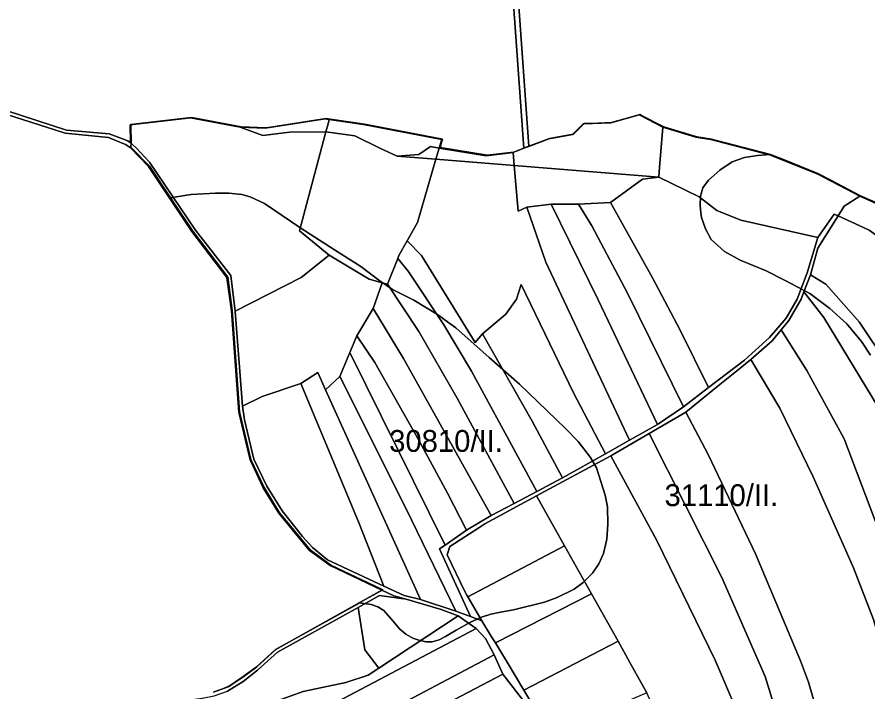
# Model space of a CAD drawing. Extents: x -535894 to -532827, y -1165802 to -1163635.
# Drawn here: x -535071 to -534487, y -1164561 to -1164098 of the extents above; entities that cross this region are included whole.
import ezdxf

# ---------------------------------------------------------------- set-up
doc = ezdxf.new("R2010")
doc.units = 0
for name, color, linetype in [('BPEJ_s', 7, 'Continuous'), ('orna_s', 7, 'Continuous'), ('ostatni_s', 7, 'Continuous'), ('PUPFL_s', 7, 'Continuous'), ('trav_porost_s', 7, 'Continuous')]:
    doc.layers.add(name, color=color, linetype=linetype)

msp = doc.modelspace()

# ---------------------------------------------------------------- linework, layer by layer
at = {"layer": 'BPEJ_s'}
for points in [[(-534935.616, -1164561.701), (-534930.369, -1164559.695), (-534925.946, -1164558.004), (-534925.446, -1164557.813), (-534915.983, -1164551.622), (-534906.33, -1164544.336), (-534893.16, -1164532.39), (-534837.757, -1164501.484), (-534836.099, -1164500.559), (-534827.97, -1164501.66), (-534823.27, -1164503.17), (-534819.077, -1164505.775), (-534813, -1164512.81), (-534808.069, -1164518.519), (-534803.96, -1164521.97), (-534799.317, -1164524.66), (-534795.2, -1164526.19), (-534790.38, -1164527.18), (-534786.08, -1164527.14), (-534781.1, -1164525.95), (-534776.72, -1164523.6), (-534769.44, -1164519.18), (-534759.64, -1164513.8), (-534752.19, -1164510.38), (-534745.78, -1164508.19), (-534739.126, -1164506.93), (-534730.05, -1164505.211), (-534708.87, -1164499.991), (-534700.23, -1164496.84), (-534688.52, -1164491.03), (-534682.31, -1164486.49), (-534675.94, -1164480.12), (-534671.48, -1164473.67), (-534668.28, -1164466.511), (-534665.98, -1164456.62), (-534665.338, -1164446.485), (-534665.67, -1164434.48), (-534667.181, -1164426.52), (-534673.149, -1164407.64), (-534677.21, -1164400.48), (-534685.81, -1164389.49), (-534694.34, -1164380.73), (-534725.95, -1164350.22), (-534746.741, -1164331.83), (-534769.679, -1164311.539), (-534774.451, -1164308.019), (-534782.34, -1164302.2), (-534798.58, -1164292.49), (-534813.16, -1164284.999), (-534822.64, -1164278.71), (-534834.98, -1164269.391), (-534853.14, -1164257.76), (-534876.848, -1164242.577), (-534901, -1164225.91), (-534910.96, -1164221.29), (-534916.61, -1164219.85), (-534925.61, -1164218.82), (-534934.669, -1164218.82), (-534951.41, -1164219.69), (-534961.495, -1164221.347), (-534965.667, -1164222.032), (-534980.193, -1164200.238), (-534992.796, -1164187.266), (-534992.657, -1164184.123), (-534992.864, -1164172.606), (-534992.881, -1164171.663), (-534951.283, -1164166.804), (-534917.176, -1164173.315), (-534900.166, -1164173.97), (-534899.694, -1164173.897), (-534858.802, -1164167.607), (-534856.129, -1164167.995), (-534832.542, -1164171.394), (-534778.846, -1164181.704), (-534779.48, -1164183.877), (-534780.07, -1164185.879), (-534780.579, -1164187.608), (-534748.266, -1164192.874), (-534729.874, -1164190.604), (-534722.509, -1164187.801), (-534705.313, -1164181.264), (-534689.018, -1164178.399), (-534684.237, -1164173.666), (-534681.635, -1164171.091), (-534672.23, -1164170.724), (-534662.759, -1164170.354), (-534644.816, -1164165.28), (-534643.356, -1164164.867)], [(-534626.941, -1164173.233), (-534642.191, -1164165.461), (-534643.356, -1164164.867), (-534644.816, -1164165.28), (-534662.759, -1164170.354), (-534672.23, -1164170.724), (-534681.635, -1164171.091), (-534684.237, -1164173.666), (-534689.018, -1164178.399), (-534705.313, -1164181.264), (-534722.509, -1164187.801), (-534729.874, -1164190.604), (-534748.266, -1164192.874), (-534780.579, -1164187.608), (-534780.07, -1164185.879), (-534779.48, -1164183.877), (-534778.846, -1164181.704), (-534832.542, -1164171.394), (-534856.129, -1164167.995), (-534858.802, -1164167.607), (-534899.694, -1164173.897), (-534900.166, -1164173.97), (-534917.176, -1164173.315), (-534951.283, -1164166.804), (-534992.881, -1164171.663), (-534992.864, -1164172.606), (-534992.657, -1164184.123), (-534992.796, -1164187.266), (-534980.193, -1164200.238), (-534965.667, -1164222.032), (-534964.702, -1164223.481), (-534950.412, -1164244.92), (-534926.32, -1164276.615), (-534923.23, -1164299.595), (-534918.262, -1164369.183), (-534910.455, -1164401.933), (-534901.354, -1164421.155), (-534890.744, -1164438.654), (-534869.801, -1164464.022), (-534855.445, -1164474.524), (-534825.523, -1164488.851), (-534819.921, -1164491.534), (-534836.099, -1164500.559), (-534837.757, -1164501.484), (-534893.16, -1164532.39), (-534906.33, -1164544.336), (-534915.983, -1164551.622), (-534925.446, -1164557.813), (-534925.946, -1164558.004), (-534930.369, -1164559.695), (-534935.616, -1164561.701)], [(-534643.356, -1164164.867), (-534642.191, -1164165.461), (-534626.941, -1164173.233), (-534604.257, -1164180.053), (-534594.057, -1164181.691), (-534590.665, -1164182.581), (-534553.695, -1164192.208)], [(-534478.19, -1164226.769), (-534491.819, -1164220.783), (-534511.744, -1164210.267), (-534521.117, -1164205.32), (-534544.673, -1164195.839), (-534553.695, -1164192.208), (-534590.665, -1164182.581), (-534594.057, -1164181.691), (-534604.257, -1164180.053), (-534626.941, -1164173.233)], [(-534484.96, -1164330.27), (-534491.235, -1164320.721), (-534501.29, -1164308.689), (-534512.831, -1164298.076), (-534526.7, -1164287.75), (-534543.58, -1164278.99), (-534556.669, -1164272.198), (-534574.4, -1164264.97), (-534585.15, -1164258.92), (-534594.3, -1164250.647), (-534598.37, -1164243.47), (-534600.979, -1164235.643), (-534601.393, -1164232.323), (-534602.001, -1164227.456), (-534601.72, -1164220.85), (-534600.201, -1164215.27), (-534596.14, -1164209.86), (-534588.42, -1164203.01), (-534579.867, -1164197.234), (-534571.45, -1164194.33), (-534562.65, -1164192.974), (-534553.695, -1164192.208), (-534544.673, -1164195.839), (-534521.117, -1164205.32), (-534511.744, -1164210.267), (-534491.819, -1164220.783), (-534478.19, -1164226.769)], [(-534553.695, -1164192.208), (-534562.65, -1164192.974), (-534571.45, -1164194.33), (-534579.867, -1164197.234), (-534588.42, -1164203.01), (-534596.14, -1164209.86), (-534600.201, -1164215.27), (-534601.72, -1164220.85), (-534602.001, -1164227.456), (-534601.393, -1164232.323), (-534600.979, -1164235.643), (-534598.37, -1164243.47), (-534594.3, -1164250.647), (-534585.15, -1164258.92), (-534574.4, -1164264.97), (-534556.669, -1164272.198), (-534543.58, -1164278.99), (-534526.7, -1164287.75), (-534512.831, -1164298.076), (-534501.29, -1164308.689), (-534491.235, -1164320.721), (-534484.96, -1164330.27)]]:
    msp.add_lwpolyline(points, dxfattribs=at)
msp.add_lwpolyline([(-534836.099, -1164500.559), (-534819.921, -1164491.534), (-534825.523, -1164488.851), (-534855.445, -1164474.524), (-534869.801, -1164464.022), (-534890.744, -1164438.654), (-534901.354, -1164421.155), (-534910.455, -1164401.933), (-534918.262, -1164369.183), (-534923.23, -1164299.595), (-534926.32, -1164276.615), (-534950.412, -1164244.92), (-534964.702, -1164223.481), (-534965.667, -1164222.032), (-534961.495, -1164221.347), (-534951.41, -1164219.69), (-534934.669, -1164218.82), (-534925.61, -1164218.82), (-534916.61, -1164219.85), (-534910.96, -1164221.29), (-534901, -1164225.91), (-534876.848, -1164242.577), (-534853.14, -1164257.76), (-534834.98, -1164269.391), (-534822.64, -1164278.71), (-534813.16, -1164284.999), (-534798.58, -1164292.49), (-534782.34, -1164302.2), (-534774.451, -1164308.019), (-534769.679, -1164311.539), (-534746.741, -1164331.83), (-534725.95, -1164350.22), (-534694.34, -1164380.73), (-534685.81, -1164389.49), (-534677.21, -1164400.48), (-534673.149, -1164407.64), (-534667.181, -1164426.52), (-534665.67, -1164434.48), (-534665.338, -1164446.485), (-534665.98, -1164456.62), (-534668.28, -1164466.511), (-534671.48, -1164473.67), (-534675.94, -1164480.12), (-534682.31, -1164486.49), (-534688.52, -1164491.03), (-534700.23, -1164496.84), (-534708.87, -1164499.991), (-534730.05, -1164505.211), (-534739.126, -1164506.93), (-534745.78, -1164508.19), (-534752.19, -1164510.38), (-534759.64, -1164513.8), (-534769.44, -1164519.18), (-534776.72, -1164523.6), (-534781.1, -1164525.95), (-534786.08, -1164527.14), (-534790.38, -1164527.18), (-534795.2, -1164526.19), (-534799.317, -1164524.66), (-534803.96, -1164521.97), (-534808.069, -1164518.519), (-534813, -1164512.81), (-534819.077, -1164505.775), (-534823.27, -1164503.17), (-534827.97, -1164501.66)], close=True, dxfattribs=at)
at = {"layer": 'orna_s'}
for points in [[(-534951.85, -1164167.07), (-534917.74, -1164173.57), (-534902.24, -1164179.24), (-534883.98, -1164176.96), (-534858.94, -1164176.7), (-534877.07, -1164244.78), (-534856.73, -1164261.58), (-534875.86, -1164276.92), (-534921.15, -1164300.08), (-534924.21, -1164275.5), (-534948.43, -1164244.35), (-534980.14, -1164197.64), (-534989.29, -1164187.7), (-534993.22, -1164184.39), (-534993.44, -1164171.93)], [(-534858.94, -1164176.7), (-534839.04, -1164179.37), (-534822, -1164188.03), (-534810.06, -1164193.46), (-534783.41, -1164195.59), (-534796.15, -1164238.96), (-534803.19, -1164251.66), (-534808.78, -1164261.74), (-534809.59, -1164263.76), (-534816.62, -1164281.45), (-534820.28, -1164280.47), (-534829.26, -1164278.07), (-534856.73, -1164261.58), (-534877.07, -1164244.78)], [(-534783.41, -1164195.59), (-534729.66, -1164199.87), (-534726.97, -1164231.26), (-534720.99, -1164228.44), (-534707.84, -1164266.29), (-534650.37, -1164388.64), (-534666.96, -1164397.98), (-534688.94, -1164356.11), (-534724.82, -1164281.62), (-534728, -1164291.7), (-534735.4, -1164302.05), (-534751.45, -1164315.56), (-534756.49, -1164321.41), (-534793.3, -1164261.64), (-534803.19, -1164251.66), (-534796.15, -1164238.96)], [(-534729.66, -1164199.87), (-534630.4, -1164207.78), (-534641.63, -1164209.34), (-534663.54, -1164225.41), (-534685.41, -1164226.35), (-534704.16, -1164226.38), (-534720.99, -1164228.44), (-534726.97, -1164231.26)], [(-534630.4, -1164207.78), (-534602.67, -1164221.46), (-534590.55, -1164230.7), (-534573.95, -1164237.35), (-534521.14, -1164249.39), (-534528.41, -1164273.53), (-534535.31, -1164291.72), (-534542.92, -1164304.7), (-534554.35, -1164317.99), (-534571.47, -1164333.62), (-534596.12, -1164352.56), (-534615.63, -1164313.03), (-534634.67, -1164277.03), (-534663.54, -1164225.41), (-534641.63, -1164209.34)], [(-534704.16, -1164226.38), (-534672.04, -1164292.08), (-534631.34, -1164377.92), (-534650.37, -1164388.64), (-534707.84, -1164266.29), (-534720.99, -1164228.44)], [(-534685.41, -1164226.35), (-534676.36, -1164241.4), (-534651.82, -1164287.55), (-534613.33, -1164365.78), (-534631.34, -1164377.92), (-534672.04, -1164292.08), (-534704.16, -1164226.38)], [(-534663.54, -1164225.41), (-534634.67, -1164277.03), (-534615.63, -1164313.03), (-534596.12, -1164352.56), (-534613.33, -1164365.78), (-534651.82, -1164287.55), (-534676.36, -1164241.4), (-534685.41, -1164226.35)], [(-534507.27, -1164234.42), (-534521.16, -1164256.66), (-534526.13, -1164274.97), (-534530.72, -1164286.68), (-534532.67, -1164291.64), (-534540.94, -1164306.3), (-534546.29, -1164312.84), (-534552.41, -1164320.35), (-534567.13, -1164333.28), (-534578.03, -1164342.06), (-534589.62, -1164351.4), (-534611.82, -1164369.29), (-534636.96, -1164383.97), (-534663.27, -1164399.34), (-534714.26, -1164426.9), (-534749.86, -1164446.14), (-534753.21, -1164448.33), (-534773.86, -1164461.8), (-534775.57, -1164467.46), (-534763.52, -1164492.61), (-534762.09, -1164495.12), (-534761.39, -1164496.32), (-534751.97, -1164512.8), (-534759.6, -1164509.93), (-534780.87, -1164463.39), (-534777.12, -1164460.78), (-534762.46, -1164450.55), (-534745.42, -1164440.45), (-534729.71, -1164432.15), (-534714.14, -1164423.92), (-534696.51, -1164414.6), (-534666.96, -1164397.98), (-534650.37, -1164388.64), (-534631.34, -1164377.92), (-534613.33, -1164365.78), (-534596.12, -1164352.56), (-534571.47, -1164333.62), (-534554.35, -1164317.99), (-534542.92, -1164304.7), (-534535.31, -1164291.72), (-534528.41, -1164273.53), (-534521.14, -1164249.39), (-534509.85, -1164233.23)], [(-534485.85, -1164244.28), (-534469.68, -1164256.06), (-534441.39, -1164280.53), (-534439.7, -1164278.38), (-534420.68, -1164291.71), (-534381.33, -1164307.72), (-534380.51, -1164314.71), (-534392.48, -1164323.34), (-534409.97, -1164335.95), (-534429.42, -1164349.98), (-534454.21, -1164364.71), (-534492.77, -1164307.32), (-534515.72, -1164281.44), (-534526.13, -1164274.97), (-534521.16, -1164256.66), (-534507.27, -1164234.42)], [(-534793.3, -1164261.64), (-534756.49, -1164321.41), (-534751.45, -1164315.56), (-534717.41, -1164375.63), (-534696.51, -1164414.6), (-534714.14, -1164423.92), (-534758.85, -1164341.14), (-534778.05, -1164309.36), (-534802.47, -1164272.58), (-534809.59, -1164263.76), (-534808.78, -1164261.74), (-534803.19, -1164251.66)], [(-534875.86, -1164276.92), (-534856.73, -1164261.58), (-534829.26, -1164278.07), (-534820.28, -1164280.47), (-534826.58, -1164298.06), (-534837.63, -1164317), (-534842.42, -1164328.36), (-534849.36, -1164344.79), (-534859.13, -1164354.02), (-534864.46, -1164342.21), (-534876.21, -1164349.78), (-534902.82, -1164358.65), (-534916.14, -1164365.28), (-534921.15, -1164300.08)], [(-534809.59, -1164263.76), (-534802.47, -1164272.58), (-534778.05, -1164309.36), (-534758.85, -1164341.14), (-534714.14, -1164423.92), (-534729.71, -1164432.15), (-534768.7, -1164359.72), (-534795.14, -1164313.94), (-534816.62, -1164281.45)], [(-534526.13, -1164274.97), (-534515.72, -1164281.44), (-534492.77, -1164307.32), (-534454.21, -1164364.71), (-534429.42, -1164349.98), (-534416.02, -1164381.41), (-534395.29, -1164442.42), (-534374.06, -1164525.31), (-534335.46, -1164704.47), (-534321.03, -1164764.37), (-534369.38, -1164771.26), (-534395.1, -1164665.47), (-534403.85, -1164623.02), (-534425.95, -1164524.31), (-534441.36, -1164472.55), (-534468.86, -1164391.61), (-534480, -1164365.41), (-534516.93, -1164304.39), (-534530.72, -1164286.68)], [(-534816.62, -1164281.45), (-534795.14, -1164313.94), (-534768.7, -1164359.72), (-534729.71, -1164432.15), (-534745.42, -1164440.45), (-534805.69, -1164332.46), (-534826.58, -1164298.06), (-534820.28, -1164280.47)], [(-534728, -1164291.7), (-534724.82, -1164281.62), (-534688.94, -1164356.11), (-534666.96, -1164397.98), (-534696.51, -1164414.6), (-534717.41, -1164375.63), (-534751.45, -1164315.56), (-534735.4, -1164302.05)], [(-534532.67, -1164291.64), (-534530.72, -1164286.68), (-534516.93, -1164304.39), (-534480, -1164365.41), (-534468.86, -1164391.61), (-534441.36, -1164472.55), (-534425.95, -1164524.31), (-534403.85, -1164623.02), (-534395.1, -1164665.47), (-534369.38, -1164771.26), (-534394.4, -1164775.14), (-534435.14, -1164602.44), (-534447.18, -1164556.51), (-534458.51, -1164505.61), (-534503.01, -1164387.73), (-534528.59, -1164340.68), (-534546.29, -1164312.84), (-534540.94, -1164306.3)], [(-534826.58, -1164298.06), (-534805.69, -1164332.46), (-534745.42, -1164440.45), (-534762.46, -1164450.55), (-534775.49, -1164425.15), (-534794.91, -1164389.11), (-534825.45, -1164335.34), (-534837.63, -1164317)], [(-534552.41, -1164320.35), (-534546.29, -1164312.84), (-534528.59, -1164340.68), (-534503.01, -1164387.73), (-534458.51, -1164505.61), (-534447.18, -1164556.51), (-534435.14, -1164602.44), (-534394.4, -1164775.14), (-534417.97, -1164782.81), (-534422.37, -1164761.45), (-534445.23, -1164674.2), (-534452.73, -1164639.92), (-534475.43, -1164538.49), (-534482.99, -1164511.95), (-534496.61, -1164476.36), (-534524.39, -1164413.79), (-534547.27, -1164366.74), (-534567.13, -1164333.28)], [(-534837.63, -1164317), (-534825.45, -1164335.34), (-534794.91, -1164389.11), (-534775.49, -1164425.15), (-534762.46, -1164450.55), (-534777.12, -1164460.78), (-534842.42, -1164328.36)], [(-534842.42, -1164328.36), (-534777.12, -1164460.78), (-534780.87, -1164463.39), (-534759.6, -1164509.93), (-534769.82, -1164506.09), (-534803.97, -1164435.37), (-534849.36, -1164344.79)], [(-534578.03, -1164342.06), (-534567.13, -1164333.28), (-534547.27, -1164366.74), (-534524.39, -1164413.79), (-534496.61, -1164476.36), (-534482.99, -1164511.95), (-534475.43, -1164538.49), (-534452.73, -1164639.92), (-534445.23, -1164674.2), (-534422.37, -1164761.45), (-534417.97, -1164782.81), (-534464.01, -1164796.91), (-534483.14, -1164727.26), (-534507.98, -1164622.35), (-534527.6, -1164554.86), (-534532.98, -1164540.25), (-534563.85, -1164466.68), (-534596.51, -1164398.57), (-534611.82, -1164369.29), (-534589.62, -1164351.4)], [(-534864.46, -1164342.21), (-534859.13, -1164354.02), (-534793.9, -1164498.24), (-534805.09, -1164495.48), (-534819.12, -1164488.91), (-534836.46, -1164444.76), (-534876.21, -1164349.78)], [(-534849.36, -1164344.79), (-534803.97, -1164435.37), (-534769.82, -1164506.09), (-534770.38, -1164505.88), (-534793.9, -1164498.24), (-534859.13, -1164354.02)], [(-534876.21, -1164349.78), (-534836.46, -1164444.76), (-534819.12, -1164488.91), (-534857.75, -1164470.83), (-534868.09, -1164462.44), (-534875.04, -1164454.94), (-534889.06, -1164437.27), (-534899.57, -1164420.22), (-534908.44, -1164401.64), (-534914.8, -1164374.59), (-534916.14, -1164365.28), (-534902.82, -1164358.65)], [(-534636.96, -1164383.97), (-534611.82, -1164369.29), (-534596.51, -1164398.57), (-534563.85, -1164466.68), (-534532.98, -1164540.25), (-534527.6, -1164554.86), (-534507.98, -1164622.35), (-534483.14, -1164727.26), (-534464.01, -1164796.91), (-534487.57, -1164805.99), (-534533.79, -1164627.84), (-534557.27, -1164551.19), (-534587.12, -1164482.93)], [(-534663.27, -1164399.34), (-534636.96, -1164383.97), (-534587.12, -1164482.93), (-534557.27, -1164551.19), (-534533.79, -1164627.84), (-534487.57, -1164805.99), (-534495.37, -1164808.4), (-534503.46, -1164810.12), (-534512.61, -1164811.26), (-534519.96, -1164775.85), (-534529.51, -1164742.37), (-534548.57, -1164664.74), (-534575.39, -1164577.77), (-534591.62, -1164539.75), (-534631.7, -1164457.63)], [(-534714.26, -1164426.9), (-534663.27, -1164399.34), (-534631.7, -1164457.63), (-534591.62, -1164539.75), (-534575.39, -1164577.77), (-534548.57, -1164664.74), (-534529.51, -1164742.37), (-534519.96, -1164775.85), (-534512.61, -1164811.26), (-534562.14, -1164816.82), (-534585.02, -1164716.41), (-534592.87, -1164689.03), (-534598.52, -1164669.31), (-534600.76, -1164662.66), (-534607.61, -1164642.33), (-534611.82, -1164629.82), (-534620.54, -1164603.95), (-534622.31, -1164599.78), (-534633.48, -1164573.56), (-534638.57, -1164562.2), (-534650.14, -1164541.51), (-534658.33, -1164526.87), (-534676.64, -1164494.15), (-534695.08, -1164461.19)], [(-534749.86, -1164446.14), (-534714.26, -1164426.9), (-534695.08, -1164461.19), (-534761.39, -1164496.32), (-534762.09, -1164495.12), (-534763.52, -1164492.61), (-534775.57, -1164467.46), (-534773.86, -1164461.8), (-534753.21, -1164448.33)], [(-534695.08, -1164461.19), (-534676.64, -1164494.15), (-534742.58, -1164527.98), (-534745.16, -1164523.82), (-534751.97, -1164512.8), (-534761.39, -1164496.32)], [(-534803.86, -1164497.99), (-534779.71, -1164504.98), (-534768.01, -1164509.35), (-534822.67, -1164545.3), (-534832.14, -1164532.75), (-534836.85, -1164503.64), (-534822.13, -1164495.45)], [(-534658.33, -1164526.87), (-534723.13, -1164560.41), (-534734.51, -1164541.31), (-534738.99, -1164533.78), (-534742.58, -1164527.98), (-534676.64, -1164494.15)], [(-534836.85, -1164503.64), (-534832.14, -1164532.75), (-534822.67, -1164545.3), (-534830, -1164550.13), (-534845.17, -1164555.12), (-534874.58, -1164561.46), (-534901.23, -1164570.96), (-534933.74, -1164580.6), (-534950.39, -1164582.04), (-534954.11, -1164567.3), (-534943.8, -1164566.05), (-534935.73, -1164564.46), (-534926.58, -1164561.08), (-534915.74, -1164554.41), (-534905.82, -1164546.8), (-534892.07, -1164534.38)], [(-534768.01, -1164509.35), (-534755.68, -1164518.03), (-534901.21, -1164594.89), (-534994.2, -1164614.17), (-535000.27, -1164571.83), (-534999.95, -1164571.8), (-534954.11, -1164567.3), (-534950.39, -1164582.04), (-534933.74, -1164580.6), (-534901.23, -1164570.96), (-534874.58, -1164561.46), (-534845.17, -1164555.12), (-534830, -1164550.13), (-534822.67, -1164545.3)], [(-534755.68, -1164518.03), (-534749.42, -1164524.99), (-534743.38, -1164536.18), (-534894.51, -1164616.18), (-534991.15, -1164635.45), (-534994.2, -1164614.17), (-534901.21, -1164594.89)], [(-534658.33, -1164526.87), (-534650.14, -1164541.51), (-534638.57, -1164562.2), (-534705.03, -1164590.78), (-534723.13, -1164560.41)], [(-534743.38, -1164536.18), (-534737.42, -1164549.39), (-534812.95, -1164589.11), (-534844.16, -1164606.93), (-534884.64, -1164626.55), (-534893.57, -1164628.99), (-534911.75, -1164633.96), (-534989.09, -1164649.85), (-534991.15, -1164635.45), (-534894.51, -1164616.18)]]:
    msp.add_lwpolyline(points, close=True, dxfattribs=at)
msp.add_lwpolyline([(-534812.95, -1164589.11), (-534737.42, -1164549.39), (-534720.94, -1164570.71)], dxfattribs=at)
at = {"layer": 'ostatni_s'}
for points in [[(-535077.79, -1164162.19), (-535037.17, -1164175.56), (-535007.7, -1164178.2), (-534995, -1164182.89), (-534993.22, -1164184.39), (-534989.29, -1164187.7), (-534980.14, -1164197.64), (-534948.43, -1164244.35), (-534924.21, -1164275.5), (-534921.15, -1164300.08), (-534916.14, -1164365.28), (-534914.8, -1164374.59), (-534908.44, -1164401.64), (-534899.57, -1164420.22), (-534889.06, -1164437.27), (-534875.04, -1164454.94), (-534868.09, -1164462.44), (-534857.75, -1164470.83), (-534819.12, -1164488.91), (-534805.09, -1164495.48), (-534793.9, -1164498.24), (-534770.38, -1164505.88), (-534769.82, -1164506.09), (-534759.6, -1164509.93), (-534751.97, -1164512.8), (-534745.16, -1164523.82), (-534742.58, -1164527.98), (-534738.99, -1164533.78), (-534734.51, -1164541.31), (-534723.13, -1164560.41), (-534705.03, -1164590.78)], [(-534720.94, -1164570.71), (-534737.42, -1164549.39), (-534743.38, -1164536.18), (-534749.42, -1164524.99), (-534755.68, -1164518.03), (-534768.01, -1164509.35), (-534779.71, -1164504.98), (-534803.86, -1164497.99), (-534812.31, -1164495.72), (-534820.5, -1164491.79), (-534856.02, -1164474.78), (-534870.38, -1164464.28), (-534891.32, -1164438.91), (-534901.93, -1164421.42), (-534911.03, -1164402.19), (-534918.83, -1164369.44), (-534923.8, -1164299.86), (-534926.89, -1164276.88), (-534950.98, -1164245.18), (-534980.76, -1164200.5), (-534993.36, -1164187.53), (-534996.47, -1164185.37), (-535008.27, -1164180.58), (-535038.07, -1164177.61), (-535078.73, -1164164.6)], [(-534936.2, -1164561.96), (-534926.03, -1164558.08), (-534916.57, -1164551.88), (-534906.91, -1164544.6), (-534893.74, -1164532.65), (-534820.5, -1164491.79), (-534812.31, -1164495.72), (-534803.86, -1164497.99), (-534822.13, -1164495.45), (-534836.85, -1164503.64), (-534892.07, -1164534.38), (-534905.82, -1164546.8), (-534915.74, -1164554.41), (-534926.58, -1164561.08)]]:
    msp.add_lwpolyline(points, dxfattribs=at)
at = {"layer": 'PUPFL_s'}
for points in [[(-534429.37, -1164029.61), (-534577.82, -1163998.3), (-534580.94, -1163997.64), (-534735.42, -1163965.07), (-534719.55, -1164186.71), (-534723.07, -1164188.05), (-534739, -1163964.32), (-535025.69, -1163903.86), (-535021.19, -1163901.16), (-534739.26, -1163960.49), (-534752.66, -1163750.06), (-534749.05, -1163747.99), (-534735.68, -1163961.24), (-534580.33, -1163993.93), (-534576.69, -1163994.7), (-534428.93, -1164025.8)], [(-535193.05, -1164004.23), (-535025.69, -1163903.86), (-534739, -1163964.32), (-534723.07, -1164188.05), (-534730.44, -1164190.85), (-534748.83, -1164193.12), (-534781.14, -1164187.86), (-534780.04, -1164184.13), (-534779.41, -1164181.96), (-534833.11, -1164171.65), (-534856.69, -1164168.25), (-534859.37, -1164167.86), (-534900.73, -1164174.23), (-534917.74, -1164173.57), (-534951.85, -1164167.07), (-534993.44, -1164171.93), (-534993.22, -1164184.39), (-534995, -1164182.89), (-535007.7, -1164178.2), (-535037.17, -1164175.56), (-535077.79, -1164162.19)], [(-535078.73, -1164164.6), (-535038.07, -1164177.61), (-535008.27, -1164180.58), (-534996.47, -1164185.37), (-534993.36, -1164187.53), (-534980.76, -1164200.5), (-534950.98, -1164245.18), (-534926.89, -1164276.88), (-534923.8, -1164299.86), (-534918.83, -1164369.44), (-534911.03, -1164402.19), (-534901.93, -1164421.42), (-534891.32, -1164438.91), (-534870.38, -1164464.28), (-534856.02, -1164474.78), (-534820.5, -1164491.79), (-534893.74, -1164532.65), (-534906.91, -1164544.6), (-534916.57, -1164551.88), (-534926.03, -1164558.08), (-534936.2, -1164561.96)]]:
    msp.add_lwpolyline(points, dxfattribs=at)
msp.add_lwpolyline([(-534735.42, -1163965.07), (-534580.94, -1163997.64), (-534577.82, -1163998.3), (-534429.37, -1164029.61), (-534426.3, -1164271.96), (-534439.05, -1164259.47), (-534446.52, -1164256.91), (-534458.72, -1164249.64), (-534465.85, -1164242.8), (-534477.05, -1164227.75), (-534492.39, -1164221.02), (-534521.68, -1164205.56), (-534554.26, -1164192.45), (-534591.23, -1164182.82), (-534594.62, -1164181.93), (-534604.82, -1164180.29), (-534627.51, -1164173.48), (-534643.92, -1164165.11), (-534663.32, -1164170.6), (-534682.2, -1164171.34), (-534689.58, -1164178.65), (-534705.88, -1164181.51), (-534719.55, -1164186.71)], close=True, dxfattribs=at)
at = {"layer": 'trav_porost_s'}
for points in [[(-534856.69, -1164168.25), (-534857.49, -1164171.28), (-534858.94, -1164176.7), (-534883.98, -1164176.96), (-534902.24, -1164179.24), (-534917.74, -1164173.57), (-534900.73, -1164174.23), (-534859.37, -1164167.86)], [(-534856.69, -1164168.25), (-534833.11, -1164171.65), (-534779.41, -1164181.96), (-534780.04, -1164184.13), (-534781.14, -1164187.86), (-534787.03, -1164186.9), (-534795.09, -1164192.41), (-534810.06, -1164193.46), (-534822, -1164188.03), (-534839.04, -1164179.37), (-534858.94, -1164176.7), (-534857.49, -1164171.28)], [(-534643.92, -1164165.11), (-534627.51, -1164173.48), (-534629.84, -1164201.15), (-534630.4, -1164207.78), (-534729.66, -1164199.87), (-534730.44, -1164190.85), (-534723.07, -1164188.05), (-534719.55, -1164186.71), (-534705.88, -1164181.51), (-534689.58, -1164178.65), (-534682.2, -1164171.34), (-534663.32, -1164170.6)], [(-534604.82, -1164180.29), (-534594.62, -1164181.93), (-534591.23, -1164182.82), (-534554.26, -1164192.45), (-534521.68, -1164205.56), (-534492.39, -1164221.02), (-534503.09, -1164227.73), (-534507.27, -1164234.42), (-534509.85, -1164233.23), (-534521.14, -1164249.39), (-534573.95, -1164237.35), (-534590.55, -1164230.7), (-534602.67, -1164221.46), (-534630.4, -1164207.78), (-534629.84, -1164201.15), (-534627.51, -1164173.48)], [(-534781.14, -1164187.86), (-534783.41, -1164195.59), (-534810.06, -1164193.46), (-534795.09, -1164192.41), (-534787.03, -1164186.9)], [(-534730.44, -1164190.85), (-534729.66, -1164199.87), (-534783.41, -1164195.59), (-534781.14, -1164187.86), (-534748.83, -1164193.12)], [(-534492.39, -1164221.02), (-534477.05, -1164227.75), (-534465.85, -1164242.8), (-534458.72, -1164249.64), (-534446.52, -1164256.91), (-534439.05, -1164259.47), (-534426.3, -1164271.96), (-534424.3, -1164273.92), (-534420.68, -1164291.71), (-534439.7, -1164278.38), (-534441.39, -1164280.53), (-534469.68, -1164256.06), (-534485.85, -1164244.28), (-534507.27, -1164234.42), (-534503.09, -1164227.73)]]:
    msp.add_lwpolyline(points, close=True, dxfattribs=at)

# ---------------------------------------------------------------- texts
at = {"layer": 'BPEJ_s'}
for s, p in [('30810/II.', (-534815.502, -1164396.679)), ('31110/II.', (-534626.391, -1164433.972))]:
    msp.add_text(s, height=15, dxfattribs=at).set_placement(p)

doc.saveas('drawing.dxf')
